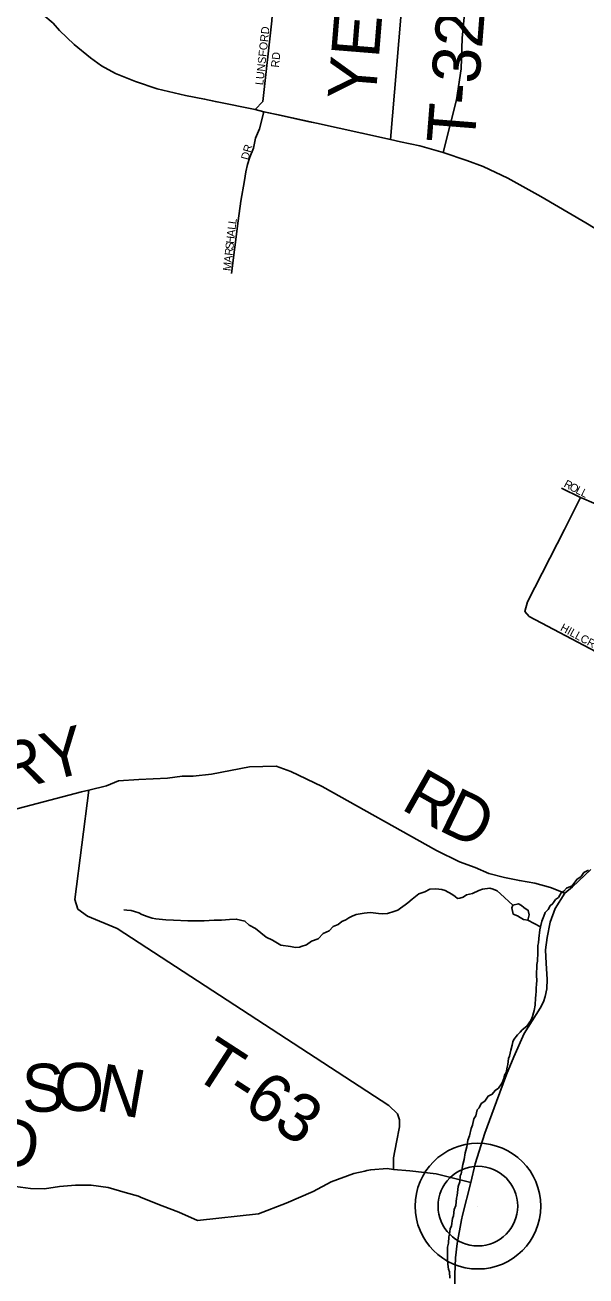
# Model space of a CAD drawing. Extents: x 1310247 to 1664935, y 235267 to 584339.
# Drawn here: x 1493957 to 1497464, y 363833 to 371649 of the extents above; entities that cross this region are included whole.
import ezdxf

# ---------------------------------------------------------------- set-up
doc = ezdxf.new("R2010")
doc.units = 0
for name, color, linetype in [('GM_X_Minor_Lake', 7, 'Continuous'), ('GM_X_Minor_River', 7, 'Continuous'), ('GM_X_State_Route', 7, 'Continuous'), ('GM_X_Township', 7, 'Continuous'), ('GM_X_Township_Road', 7, 'Continuous'), ('GM_X_Township_Road_Text', 7, 'Continuous'), ('GM_X_Township_ROW', 7, 'Continuous'), ('GM_X_Township_Subdivision', 7, 'Continuous'), ('GM_X_Township_Subdivision_Text', 7, 'Continuous'), ('GM_X_Unincorporated', 7, 'Continuous'), ('GM_X_Unincorporated_Location', 7, 'Continuous')]:
    doc.layers.add(name, color=color, linetype=linetype)

msp = doc.modelspace()

# ---------------------------------------------------------------- linework, layer by layer
at = {"layer": 'GM_X_Minor_Lake'}
for points in [[(1497099.5, 366057.1), (1497108.1, 366089), (1497102.6, 366117.2), (1497074.8, 366135.8), (1497061, 366148.1), (1497043.1, 366158.4), (1497006.9, 366151), (1497000.6, 366133.1), (1497007.9, 366092.8)], [(1497007.9, 366092.8), (1497035.9, 366084.3), (1497051.7, 366072), (1497073.5, 366059.5), (1497099.5, 366057.1)], [(1497099.5, 366057.1), (1497180, 366015.3)]]:
    msp.add_lwpolyline(points, dxfattribs=at)
at = {"layer": 'GM_X_Minor_River'}
for points in [[(1497479.9, 366367.9), (1497451.5, 366354.3), (1497432.9, 366328.5), (1497406.5, 366310.8), (1497377.6, 366271.1), (1497343.2, 366255.6), (1497324.8, 366237.9), (1497308.5, 366226.1), (1497291.9, 366198.2), (1497273.5, 366184.5), (1497257, 366160.7)], [(1497006.9, 366151), (1496928.9, 366220.1), (1496909.2, 366240.5), (1496883.2, 366251), (1496863.2, 366255.3), (1496816.9, 366250.1), (1496794.6, 366242.5), (1496754.1, 366223.1), (1496717.8, 366213.6), (1496695.4, 366200), (1496675.2, 366194.3), (1496661.1, 366192.5), (1496645.2, 366204.8), (1496625.4, 366219.2), (1496583.6, 366242.1), (1496563.6, 366248.4), (1496525.5, 366251.1), (1496487.3, 366249.8), (1496456.8, 366234.2), (1496418.4, 366220.8), (1496377.6, 366187.3), (1496351, 366163.7), (1496332.7, 366151.9), (1496304.3, 366132.3), (1496287.9, 366118.5), (1496263.7, 366110.9), (1496223.2, 366097.5), (1496189, 366096.1), (1496167, 366098.5), (1496132.9, 366103.1), (1496114.8, 366103.4), (1496076.5, 366100), (1496028.1, 366090.8), (1496001.8, 366081.2), (1495981.6, 366071.5), (1495963.2, 366057.8), (1495936.9, 366048.2), (1495914.5, 366028.5), (1495884.1, 366016.9), (1495857.5, 365989.2), (1495821, 365973.8), (1495790.3, 365940.2), (1495747.8, 365924.8), (1495717.2, 365901.2), (1495688.9, 365893.7), (1495672.7, 365887.9), (1495648.6, 365886.3), (1495616.5, 365890.9), (1495556.4, 365900), (1495504.7, 365931), (1495464.8, 365949.8), (1495397.5, 366005.2), (1495357.7, 366026), (1495332, 366050.5), (1495304, 366057), (1495278, 366063.5), (1495235.7, 366060.2), (1495185.4, 366057.1), (1495139.1, 366055.9), (1495076.8, 366052.9), (1494974.3, 366052.7), (1494885.9, 366056.2), (1494837.7, 366059), (1494775.5, 366064.1), (1494751.5, 366068.6), (1494721.5, 366079.1), (1494687.6, 366091.8), (1494667.7, 366102.1), (1494641.7, 366110.6), (1494621.7, 366117), (1494593.6, 366119.5), (1494575.6, 366121.8)], [(1497257, 366160.7), (1497240.7, 366146.9), (1497228.2, 366123), (1497209.8, 366105.2), (1497201.3, 366081.2), (1497188.7, 366049.3), (1497180, 366015.3), (1497175.7, 365995.2), (1497168.6, 365941.1), (1497166.2, 365915), (1497163.8, 365897), (1497163.1, 365854.8), (1497160.1, 365800.6), (1497155.7, 365778.5), (1497154.4, 365708.2), (1497155.9, 365682), (1497155.4, 365653.9), (1497153, 365633.9), (1497152.7, 365613.8), (1497150.1, 365585.7), (1497147.9, 365571.6), (1497147.1, 365525.4), (1497140.4, 365491.4), (1497136.1, 365477.4), (1497129.7, 365455.4), (1497119.2, 365429.5), (1497094.4, 365393.7), (1497065.9, 365372.1), (1497051.5, 365356.2), (1497035.2, 365340.5), (1497012.5, 365310.7), (1497006.2, 365296.7), (1497001.8, 365274.7), (1496993.2, 365244.7), (1496986.5, 365206.6), (1496980.2, 365192.7), (1496975.5, 365154.6), (1496971.2, 365138.6), (1496964.6, 365104.5), (1496954.2, 365088.6), (1496949.8, 365066.6), (1496939.3, 365040.6), (1496916.6, 365006.8), (1496896.2, 364993.1), (1496877.7, 364969.3), (1496853.4, 364957.7), (1496832.7, 364925.9), (1496808.3, 364910.2), (1496795.8, 364884.3), (1496783.5, 364870.5), (1496774.8, 364834.4), (1496762.4, 364814.5), (1496753.6, 364774.5), (1496745.2, 364754.5), (1496736.3, 364708.5), (1496725.8, 364682.5), (1496719, 364640.4), (1496712.5, 364616.4), (1496708.3, 364602.4), (1496701.5, 364560.3), (1496694.9, 364530.3), (1496683.8, 364472.2), (1496677.5, 364458.3), (1496674.9, 364422.1), (1496664.3, 364392.2), (1496659.2, 364336), (1496654.9, 364320), (1496650.1, 364273.8), (1496639.5, 364247.9), (1496634.8, 364209.8), (1496630.5, 364191.8), (1496623.6, 364145.7), (1496615.3, 364127.7), (1496610.6, 364093.6), (1496606.3, 364077.6), (1496603.6, 364037.5), (1496599.1, 364013.4), (1496597.6, 363931.1), (1496601.2, 363906.9), (1496604.7, 363876.7), (1496610.4, 363858.5), (1496613.7, 363820.2)]]:
    msp.add_lwpolyline(points, dxfattribs=at)
at = {"layer": 'GM_X_State_Route'}
for points in [[(1494011, 371763.6), (1494021.4, 371755), (1494068, 371714.1), (1494133.4, 371660.3), (1494172.1, 371614.3), (1494265.4, 371528.2), (1494367.4, 371444.9), (1494436.3, 371393.2), (1494522.5, 371345.8), (1494647.4, 371295.6), (1494783.8, 371251.1), (1494960.4, 371209.4), (1495079.6, 371186.5), (1495156.7, 371169.6)], [(1495156.7, 371169.6), (1495158.5, 371169.2), (1495395.5, 371121.2), (1495450.2, 371106.1), (1495540.7, 371087.9), (1495725.2, 371047.3)], [(1495725.2, 371047.3), (1495779.7, 371035.3), (1496062.8, 370974.5), (1496241.8, 370934.9), (1496304.3, 370920.3), (1496425, 370895.4), (1496570.8, 370852.7), (1496718.9, 370802.2), (1496820.7, 370764.3), (1496975.8, 370691.9), (1497181.1, 370578.1), (1497462.2, 370414.3), (1497697.3, 370272.3), (1497727.7, 370253.9), (1497926, 370152.1), (1497965.9, 370130.5)], [(1496692.3, 364212.2), (1496743.2, 364416.3), (1496770.6, 364533.4), (1496831.7, 364724.5), (1496905, 364923.3), (1496966.6, 365092.3), (1497013.7, 365201.8), (1497078.1, 365348.1), (1497178.4, 365505.7), (1497198.6, 365546.6), (1497209.5, 365579.2), (1497220, 365628.1), (1497221.4, 365687.8), (1497215.2, 365786), (1497210.5, 365870.3), (1497220.8, 365948.7), (1497240.2, 366044.8), (1497271.3, 366128.7), (1497331.9, 366225), (1497379.2, 366265.1), (1497493.3, 366373.7)], [(1496660.2, 361120.8), (1496669.2, 361214.5), (1496680.3, 361318.8), (1496685, 361410.1), (1496679.5, 361558.5), (1496667.3, 361730.4), (1496648.6, 361893.4), (1496619.8, 362202.6), (1496602.1, 362414.9), (1496597.4, 362508), (1496590.9, 362663.5), (1496596.9, 362790.6), (1496604.1, 362923.8), (1496613.5, 363087.9), (1496629.8, 363309.8), (1496641.4, 363507.5), (1496643.1, 363614.3), (1496644, 363842.5), (1496648.6, 363945.9), (1496658.9, 364037.1), (1496685.4, 364184.3), (1496692.3, 364212.2)]]:
    msp.add_lwpolyline(points, dxfattribs=at)
at = {"layer": 'GM_X_Township'}
for points in [[(1497697.3, 370272.3), (1497462.2, 370414.3), (1497181.1, 370578.1), (1496975.9, 370691.9), (1496820.7, 370764.3), (1496718.9, 370802.3), (1496570.7, 370852.7), (1496425, 370895.3), (1496304.3, 370920.3), (1496241.8, 370934.9), (1496062.8, 370974.5), (1495779.6, 371035.3), (1495540.8, 371087.9), (1495450.2, 371106.1), (1495395.5, 371121.2), (1495158.5, 371169.2), (1495079.5, 371186.5), (1494960.4, 371209.4), (1494783.8, 371251.1), (1494647.4, 371295.6), (1494522.5, 371345.8), (1494436.3, 371393.2), (1494367.4, 371444.9), (1494265.4, 371528.2), (1494172.1, 371614.3), (1494133.4, 371660.3)], [(1494133.4, 371660.3), (1494172.1, 371614.3), (1494265.4, 371528.2), (1494367.4, 371444.9), (1494436.3, 371393.2), (1494522.5, 371345.8), (1494647.4, 371295.6), (1494783.8, 371251.1), (1494960.4, 371209.4), (1495079.5, 371186.5), (1495158.5, 371169.2), (1495395.5, 371121.2), (1495450.2, 371106.1), (1495540.8, 371087.9), (1495779.6, 371035.3), (1496062.8, 370974.5), (1496241.8, 370934.9), (1496304.3, 370920.3), (1496425, 370895.3), (1496570.7, 370852.7), (1496718.9, 370802.3), (1496820.7, 370764.3), (1496975.9, 370691.9), (1497181.1, 370578.1), (1497462.2, 370414.3), (1497697.3, 370272.3)]]:
    msp.add_lwpolyline(points, dxfattribs=at)
at = {"layer": 'GM_X_Township_Road'}
for points in [[(1496241.8, 370934.9), (1496420.3, 373055.5)], [(1492512.7, 366401.1), (1493524.4, 366652.8), (1494310.8, 366858.7), (1494355.9, 366868.4), (1494466.3, 366896.1), (1494541.6, 366927.9), (1494668.5, 366936.1), (1494848.6, 366944.3), (1494938.6, 366956.6), (1495008.2, 366956.6), (1495122.8, 366968.9), (1495360.2, 367013.9), (1495528, 367018), (1495618, 366985.3), (1495814.5, 366891.1), (1496528.7, 366492.1), (1496674, 366420.5), (1496772.2, 366384.6), (1496857.1, 366347.8), (1496955.3, 366322.2), (1497047.4, 366303.8), (1497144.6, 366288.4), (1497242.9, 366259.8), (1497331.9, 366225)], [(1496261.7, 364499.2), (1496260.2, 364571.7), (1496278.6, 364669.1), (1496297.9, 364765.6), (1496297.9, 364807.9), (1496285.9, 364845.6), (1496231.7, 364898.8), (1494532.6, 366003.4), (1494348.3, 366080.3), (1494286.9, 366125.3), (1494268.4, 366185.9), (1494355.9, 366868.4)], [(1492434.3, 364558.3), (1492567.7, 364548.7), (1493804.9, 364404.1), (1493991.5, 364379.1), (1494078.1, 364377.1), (1494172.4, 364392.5), (1494272.5, 364400.2), (1494370.6, 364400.2), (1494477.6, 364385.2), (1494582.3, 364354.1), (1494667, 364331), (1494684.1, 364324.1)], [(1496095, 364491.3), (1496118.2, 364496.4), (1496220.5, 364503.8), (1496261.7, 364499.2), (1496363.7, 364490.6), (1496526.7, 364471.1), (1496743.2, 364416.3)]]:
    msp.add_lwpolyline(points, dxfattribs=at)
at = {"layer": 'GM_X_Township_ROW'}
msp.add_lwpolyline([(1494684.1, 364324.1), (1494815.2, 364271.3), (1494919.1, 364230.9), (1495034.6, 364180.8), (1495416, 364222.1), (1495590, 364287.7), (1495758.1, 364361.5), (1495871.9, 364420.7), (1496013.4, 364473.2), (1496081.2, 364488.2), (1496095, 364491.3)], dxfattribs=at)
at = {"layer": 'GM_X_Township_Subdivision'}
for points in [[(1496570.8, 370852.7), (1496655.1, 371181.6), (1496682.7, 371374.8), (1496689.6, 371567.9), (1496710.3, 371785.2), (1496775.8, 372285.3)], [(1495395.5, 371121.2), (1495444.2, 371172.3), (1495500.2, 371675.5), (1495512.4, 371856.3)], [(1495248.5, 370096.5), (1495289.4, 370426.2), (1495306.8, 370548.1), (1495328.3, 370677.8), (1495337.8, 370731.7), (1495349, 370777.5), (1495362.3, 370823.2), (1495385.8, 370878.8), (1495399, 370943.3), (1495423.1, 371000), (1495450.2, 371106.1)], [(1497914.7, 367490.6), (1497887, 367512.6), (1497833.3, 367555.4), (1497747.8, 367606.3), (1497527.5, 367731.9), (1497108.9, 367954.4), (1497082.3, 367985), (1497097.6, 368044.8), (1497330.4, 368497.6), (1497429.6, 368697.4)], [(1497310, 368755.9), (1497429.6, 368697.4), (1497450.8, 368688.1)], [(1497450.8, 368688.1), (1497641.5, 368604.5)]]:
    msp.add_lwpolyline(points, dxfattribs=at)
at = {"layer": 'GM_X_Unincorporated'}
for radius in [392.8, 249]:
    msp.add_circle((1496788.5, 364269.6), radius, dxfattribs=at)
at = {"layer": 'GM_X_Unincorporated_Location'}
msp.add_line((1496788.5, 364269.6), (1496788.5, 364269.6), dxfattribs=at)

# ---------------------------------------------------------------- texts
at = {"layer": 'GM_X_Township_Road_Text'}
for s, rotation, p in [('YELTON RD', 85.36804, (1496147.3, 371170.2)), ('T-323', 85.49258, (1496766.5, 370899.8)), ('BERRY', 14.28523, (1493022.9, 366647.6)), ('R', 330.45069, (1496299.6, 366754.3)), ('D', 334.14889, (1496532.4, 366623.2)), ('T-63', 327.09526, (1494992.1, 365087.1)), ('O', 1.26959, (1494143.6, 364860.9)), ('S', 1.32251, (1493941.3, 364856.2)), ('N', 349.94539, (1494391.9, 364867.9)), ('RD', 353.05915, (1493452.6, 364566.9))]:
    msp.add_text(s, height=300, rotation=rotation, dxfattribs=at).set_placement(p)
at = {"layer": 'GM_X_Township_Subdivision_Text'}
for s, rotation, p in [('LUNSFORD', 83.74345, (1495446, 371271.7)), ('RD', 83.99398, (1495543.9, 371381.6)), ('DR', 74.47244, (1495353.9, 370802.4)), ('L', 83.59868, (1495272.7, 370368.1)), ('L', 81.49895, (1495276.5, 370402.6)), ('H', 83.58257, (1495262.8, 370280.6)), ('A', 83.56084, (1495267.7, 370324.4)), ('R', 83.59096, (1495254.5, 370206.3)), ('S', 83.59868, (1495258.9, 370245.7)), ('A', 83.59332, (1495249.5, 370162.6)), ('M', 83.57533, (1495243.6, 370110.1)), ('R', 331.97965, (1497321, 368766.6)), ('O', 331.98208, (1497356, 368748)), ('L', 331.98074, (1497394.8, 368727.3)), ('L', 333.59939, (1497427.3, 368710.1)), ('HILLCREST', 331.38966, (1497299.1, 367868.9))]:
    msp.add_text(s, height=50, rotation=rotation, dxfattribs=at).set_placement(p)

doc.saveas('drawing.dxf')
